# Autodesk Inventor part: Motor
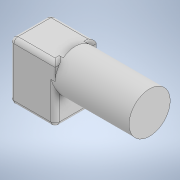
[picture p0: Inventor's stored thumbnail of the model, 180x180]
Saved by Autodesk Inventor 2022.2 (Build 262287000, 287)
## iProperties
Created: 2022-03
Part Number: Motor
Material: Generic
Document SubType Name: Modeling
Designer: cl
Density: 1 g/cm^3
Appearance: Default
Author: cl
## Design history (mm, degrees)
sketch "Sketch1"
  geometry: L1 (0, 0)-(110, 0); L2 (110, 0)-(110, -100); L3 (110, -100)-(0, -100); L4 (0, -100)-(0, 0)
  constraints: 8 end point, 2 parallel, 1 horizontal, 1 perpendicular
  dimensions: "d0" = 110 distance of L2.end L3.end; "d1" = 100 distance of L1.end L2.end
extrude "Extrusion1" new body sketch "Sketch1" distance "d2" = 140; taper "d3" = 0 deg
sketch "Sketch2"
  geometry: L1 (0, 0)-(100, 0) reference; L2 (0, 0)-(0, 140) reference; C1 r 50 at (50, 100)
  constraints: 1 centre point, 1 tangent
  dimensions: "d4" = 100 diameter of C1; "d5" = 100 distance from line of L1 C1.centre
extrude "Extrusion2" join sketch "Sketch2" distance "d6" = 180; taper "d7" = 0 deg
fillet "Fillet1" dims "d8" = 10
body "Solid1"
